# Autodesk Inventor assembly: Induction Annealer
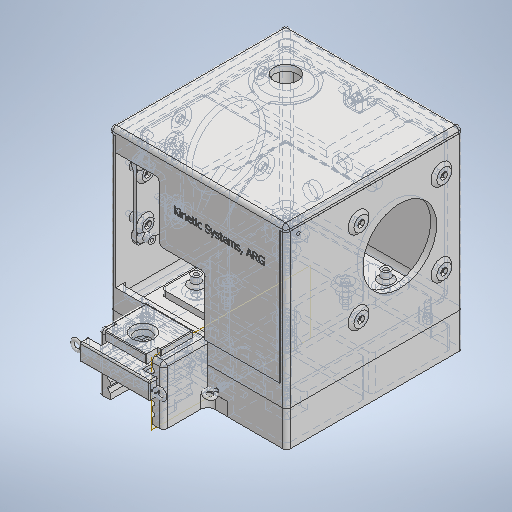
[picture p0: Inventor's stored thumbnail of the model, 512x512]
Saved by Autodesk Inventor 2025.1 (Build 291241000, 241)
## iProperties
Created: 2023-12
Part Number: Induction Annealer
Document SubType Name: Assembly
Designer: Andrew
Author: Andrew
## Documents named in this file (10)
- E:\KS ARG\CAD\Induction Annealer\Induction Annealer.iam
- E:\KS ARG\CAD\Induction Annealer\Box.ipt
- E:\KS ARG\CAD\Induction Annealer\Lid.ipt
- E:\KS ARG\CAD\Induction Annealer\Base.ipt
- E:\KS ARG\CAD\Induction Annealer\TPU Case Guide.ipt
- E:\KS ARG\CAD\Induction Annealer\TPU Pad.ipt
- E:\KS ARG\CAD\Induction Annealer\Timer Tray.ipt
- E:\KS ARG\CAD\Induction Annealer\Induction Tray.ipt
- E:\KS ARG\CAD\Induction Annealer\9496T33_Routing Eyebolt for Wood - Not for Lifting\9496T33_Routing Eyebolt for Wood - Not for Lifting.ipt
- E:\KS ARG\CAD\Induction Annealer\Front Box.ipt
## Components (12 placed, 9 different names)
1. Box:1 — Mate:1, Mate:2, Flush:1, Mate:4, Flush:4, Flush:5, Mate:10, Mate:11, Mate:12, Mate:13, Mate:14, Mate:15, Mate:29, Mate:32
2. Lid:1 — Mate:14, Mate:15
3. Base:1 — Mate:4, Flush:4, Flush:5, Mate:25, Mate:26, Mate:27, Mate:28, Flush:6, Mate:33, Mate:46
4. TPU Case Guide:1 — Mate:37, Mate:38, Mate:39
5. TPU Pad:1 — Mate:40, Mate:41, Mate:42, Mate:43, Mate:44, Mate:45
6. Timer Tray:1 — Mate:10, Mate:11, Mate:32
7. Induction Tray:1 — Mate:12, Mate:13, Mate:29
8. 9496T33_Routing Eyebolt for Wood - Not for Lifting:1 — Mate:42, Mate:43
9. 9496T33_Routing Eyebolt for Wood - Not for Lifting:2 — Mate:44, Mate:45
10. 9496T33_Routing Eyebolt for Wood - Not for Lifting:3 — Mate:25, Mate:26
11. 9496T33_Routing Eyebolt for Wood - Not for Lifting:4 — Mate:27, Mate:28
12. Front Box:1
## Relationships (30: Mate 26, Flush 4)
- Mate:1: Box:1
- Mate:2: Box:1
- Flush:1: Box:1
- Mate:4: Box:1 ↔ Base:1
- Flush:4: Box:1 ↔ Base:1
- Flush:5: Box:1 ↔ Base:1
- Mate:10: Box:1 ↔ Timer Tray:1
- Mate:11: Box:1 ↔ Timer Tray:1
- Mate:12: Box:1 ↔ Induction Tray:1
- Mate:13: Box:1 ↔ Induction Tray:1
- Mate:14: Box:1 ↔ Lid:1
- Mate:15: Box:1 ↔ Lid:1
- Mate:25: Base:1 ↔ 9496T33_Routing Eyebolt for Wood - Not for Lifting:3
- Mate:26: Base:1 ↔ 9496T33_Routing Eyebolt for Wood - Not for Lifting:3
- Mate:27: Base:1 ↔ 9496T33_Routing Eyebolt for Wood - Not for Lifting:4
- Mate:28: Base:1 ↔ 9496T33_Routing Eyebolt for Wood - Not for Lifting:4
- Mate:29: Box:1 ↔ Induction Tray:1
- Mate:32: Box:1 ↔ Timer Tray:1
- Flush:6: Base:1
- Mate:33: Base:1
- Mate:37: TPU Case Guide:1
- Mate:38: TPU Case Guide:1
- Mate:39: TPU Case Guide:1
- Mate:40: TPU Pad:1
- Mate:41: TPU Pad:1
- Mate:42: TPU Pad:1 ↔ 9496T33_Routing Eyebolt for Wood - Not for Lifting:1
- Mate:43: TPU Pad:1 ↔ 9496T33_Routing Eyebolt for Wood - Not for Lifting:1
- Mate:44: TPU Pad:1 ↔ 9496T33_Routing Eyebolt for Wood - Not for Lifting:2
- Mate:45: TPU Pad:1 ↔ 9496T33_Routing Eyebolt for Wood - Not for Lifting:2
- Mate:46: Base:1
